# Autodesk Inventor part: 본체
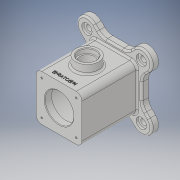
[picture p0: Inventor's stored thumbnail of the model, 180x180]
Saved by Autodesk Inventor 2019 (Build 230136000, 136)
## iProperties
Created: 2021-01
Part Number: 본체
Material: 일반
Document SubType Name: Modeling
Designer: 3DPRO15
Density: 1 g/cm^3
Appearance: 기본값
Mass: 387.376 g
Surface Area: 857.673 cm^2
Volume: 387.376 cm^3
Author: 3DPRO15
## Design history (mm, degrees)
sketch "스케치2"
  geometry: L1 (48, -48)-(-48, -48); L2 (-48, -48)-(-48, 48); L3 (-48, 48)-(48, 48); L4 (48, 48)-(48, -48); L5 (48, -48)-(-48, 48); L6 (-48, -48)-(48, 48); 1 further point
  constraints: 12 end point, 2 midpoint, 2 parallel, 1 horizontal, 1 perpendicular
  dimensions: "d9" = 96 distance of L2.end L3.end; "d10" = 96 distance of L1.end L2.end
extrude "돌출1" new body sketch "스케치2" distance "d11" = 12; taper "d12" = 0 deg
sketch "스케치3"
  geometry: L1 (-48, -48)-(48, -48) reference; L2 (48, -48)-(48, 48) reference; L3 (48, 48)-(-48, 48) reference; L4 (-48, 48)-(-48, -48) reference; L5 (-60.104, 34.648)-(-48, 22.544); L6 (-34.648, 60.104)-(-22.544, 48); L7 (-47.376, 47.376)-(0, 0); L8 (0, -93.891)-(0, 101.347) reference; A1 r 18 centre (-47.376, 47.376) between (-34.648, 60.104) and (-60.104, 34.648); 1 further point
  constraints: 8 end point, 2 coincident, 2 parallel, 2 point on circle, 2 point on line, 1 centre point
  dimensions: "d15" = 18 radius of A1; "d132" = 67 distance of L7.start L7.end; "d133" = 45 deg angle of L8 L7; "d135" = 36 distance between parallel lines of L5 L6
  node "투영된 루프1"
sketch "스케치4"
  geometry: L1 (40, 40)-(-40, 40); L2 (-40, 40)-(-40, -40); L3 (-40, -40)-(40, -40); L4 (40, -40)-(40, 40); L5 (40, 40)-(-40, -40); L6 (-40, 40)-(40, -40); 1 further point
  constraints: 12 end point, 2 midpoint, 2 parallel, 1 horizontal, 1 perpendicular
  dimensions: "d18" = 80 distance of L3.end L2.end; "d19" = 80 distance of L2.end L1.end
extrude "돌출3" join sketch "스케치4" distance "d20" = 96; taper "d21" = 0 deg
sketch "스케치5"
  geometry: C1 r 25 at (0, 0); 1 further point
  constraints: 1 centre point, 1 coincident
  dimensions: "d22" = 50 diameter of C1
extrude "돌출4" cut sketch "스케치5" distance "d23" = 12; taper "d24" = 0 deg
sketch "스케치6"
  geometry: C1 r 25 at (0, 0) reference; 2 further points
  constraints: 1 coincident
hole "구멍1" sketch "스케치6" at (0, 0) diameter "d25" = 70; stored, may be unused: countersink angle "d29" = 90 deg, drill point angle "d31" = 0 deg; dims "d26" = 6, "d27" = 4, "d28" = 2, "d30" = 84
sketch "스케치7"
  geometry: C1 r 35 at (0, 0) reference; 2 further points
  constraints: 1 coincident
hole "구멍2" sketch "스케치7" at (0, 0) diameter "d32" = 50; stored, may be unused: countersink angle "d36" = 90 deg, drill point angle "d38" = 0 deg; dims "d33" = 6, "d34" = 4, "d35" = 2, "d37" = 84
sketch "스케치8"
  geometry: 2 further points
  dimensions: "d39" = 30 horizontal distance of point (0, 0) point (-30, 30); "d40" = 30 horizontal distance of point (0, 0) point (-30, 30)
hole "구멍3" sketch "스케치8" at (-30, 30) diameter "d41" = 3.242; stored, may be unused: countersink angle "d45" = 90 deg, drill point angle "d47" = 118 deg; dims "d42" = 8, "d43" = 4, "d44" = 2, "d46" = 10
fillet "모깎기1" dims "d65" = 10
fillet "모깎기2" dims "d66" = 3
fillet "모깎기3" dims "d67" = 3
extrude "돌출6" join sketch "스케치3" distance "d83" = 12; taper "d84" = 0 deg
fillet "모깎기6" dims "d88" = 20
fillet "모깎기7" dims "d89" = 3
sketch "스케치12"
  geometry: L1 (15.74, 15)-(44.26, 15) reference; L2 (92.376, 3)-(66.77, 3) reference; C1 r 20 at (30, -44); 3 further points
  constraints: 1 centre point, 1 midpoint, 1 vertical alignment
  dimensions: "d90" = 40 diameter of C1; "d91" = 47 distance from line of L2 C1.centre
extrude "돌출7" join sketch "스케치12" distance "d92" = 15; taper "d93" = 0 deg
sketch "스케치13"
  geometry: C1 r 20 at (0, 0) reference; 2 further points
  constraints: 1 coincident
hole "구멍6" sketch "스케치13" at (0, 0) diameter "d94" = 25; stored, may be unused: countersink angle "d98" = 90 deg, drill point angle "d100" = 0 deg; dims "d95" = 8, "d96" = 30, "d97" = 8, "d99" = 10
sketch "스케치14"
  geometry: L1 (15.74, 15)-(44.26, 15) reference; L2 (60, -93)-(0, -93) reference; 3 further points
  constraints: 1 midpoint, 1 vertical alignment, 1 other
  dimensions: "d102" = 10 distance from line of L2 point (30, -83)
feature "엠보싱1" sketch "스케치14" dims "d9" = 96, "d10" = 96, "d18" = 80, "d19" = 80, "d103" = 0.5, "d104" = 0
chamfer "모따기1" distance "d105" = 1; stored, may be unused: second distance "d106" = 2, angle "d107" = 45 deg
fillet "모깎기8" dims "d118" = 3
node "작업 평면1"
sketch "스케치16"
  geometry: L1 (0, 0)-(47.376, 47.376); L2 (0, 0)-(67, 0); 1 further point
  constraints: 4 end point, 1 coincident, 1 equal length, 1 horizontal
  dimensions: "d120" = 67 distance of L1.start L1.end; "d121" = 45 deg angle of L2 L1
hole "구멍8" sketch "스케치16" at (47.376, 47.376) diameter "d122" = 10; stored, may be unused: countersink angle "d126" = 90 deg, drill point angle "d128" = 118 deg; dims "d123" = 6, "d124" = 18, "d125" = 4, "d127" = 8
node "솔리드1"
pattern_linear "직사각형 패턴1" dims "d50" = 60, "d53" = 60
pattern_circular "원형 패턴1" dims angle "d86" = 360 deg
mirror "미러3"
pattern_circular "원형 패턴3" dims angle "d130" = 360 deg
other parameters: "d0" = 134, "d13" = 36, "d119" = 54
